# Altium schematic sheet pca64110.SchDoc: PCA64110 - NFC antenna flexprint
size A4; Revision: 1.0.0; SheetNumber: 1; SheetTotal: 1; Author: TORS; DrawnBy: TORS; ProjectNumber: 4397; DocumentSize: A4; PCBRevision: 0018TORS; PCAName: PCA64110; PCBNumber: 400148
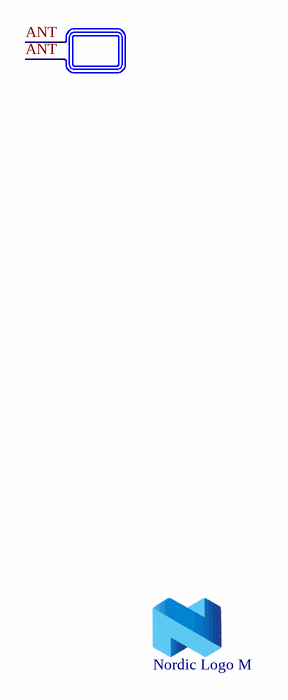
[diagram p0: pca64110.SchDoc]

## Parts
A1  NFC_ANT_Listener-6  [NFC_ANT_Listener-6]  (value not drawn)  (no BOM)
LOGO1  Nordic Logo M  [NORDIC_LOGO_M]  (no BOM)

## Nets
ANT: A1.1 A1.2

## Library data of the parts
A1 = NFC_ANT_Listener-6: NFC Antenna Listener-6; Artikkelnr Noca: N.A.
LOGO1 = Nordic Logo M: Nordic Logo, medium size; Artikkelnr Noca: N.A.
